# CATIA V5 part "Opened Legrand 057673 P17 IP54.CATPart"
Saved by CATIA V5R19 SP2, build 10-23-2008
Part number: Opened Legrand 057673 P17 IP54
Definition: design
Nomenclature: Opened Legrand 057673 P17 IP54
Source: Unknown
Bounding box of the stored display mesh (mm): x 43 to 136.5, y 29 to 81, z 12 to 76
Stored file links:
  Z:\fausse table rondelle-20220905T211342Z-001\fausse table rondelle\Opened Legrand 057673 P17 IP54.CATPart
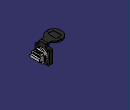
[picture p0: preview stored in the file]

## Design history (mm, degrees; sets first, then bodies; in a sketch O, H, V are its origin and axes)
AxisSystem1: origin (0, 0, 0), X (1, 0, 0), Y (0, 1, 0), Z (0, 0, 1)
Body1 "Opened Legrand 057673 P17 IP54" (main body)
  Solid1: solid without history
Body2 "Opened Front"
  Solid2: solid without history
Body3 "Opened Socket"
  Solid3: solid without history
